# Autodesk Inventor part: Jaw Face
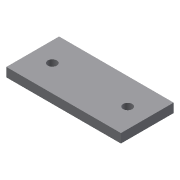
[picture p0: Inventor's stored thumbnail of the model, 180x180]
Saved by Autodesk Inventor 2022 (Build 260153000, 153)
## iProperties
Created: 2002-02
Part Number: Jaw Face
Document SubType Name: Modeling
Designer: ***
Density: 1 g/cm^3
Material: Generic
Appearance: Default
Control State: 0
Master: False
Checked Out: False
Shininess: 77.0
Length Units: 11269
Angle Units: 11279
Time Units: 11290
Mass Units: 11283
Length Display Precision: 3
Angle Display Precision: 2
Compacted: True
Density: 0.0
Volumn: 0.0
Area: 0.0
PropertySet Name: Model Information
Author: ***
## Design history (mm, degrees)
sketch "Sketch1"
  geometry: L1 (-79.661, -8.43)-(-3.661, -8.43); L2 (-3.661, -8.43)-(-3.661, -43.43); L3 (-3.661, -43.43)-(-79.661, -43.43); L4 (-79.661, -43.43)-(-79.661, -8.43); C1 r 3 at (-66.661, -25.93); C2 r 3 at (-16.661, -25.93)
  constraints: 8 end point, 2 centre point, 2 parallel, 1 equal radius, 1 horizontal, 1 perpendicular
  dimensions: "d0" = 76 distance of L2.end L3.end; "d1" = 6 diameter of C1; "d2" = 50 distance of C2.centre C1.centre; "d3" = 35 distance of L1.end L2.end; "d4" = 17.5 distance from line of L3 C2.centre; "d5" = 13 distance from line of L2 C2.centre; "d6" = 13 distance from line of L4 C1.centre
extrude "Extrusion1" new body sketch "Sketch1" stored distance "d7" = 6; taper "d8" = 0 deg
body "Solid1"
